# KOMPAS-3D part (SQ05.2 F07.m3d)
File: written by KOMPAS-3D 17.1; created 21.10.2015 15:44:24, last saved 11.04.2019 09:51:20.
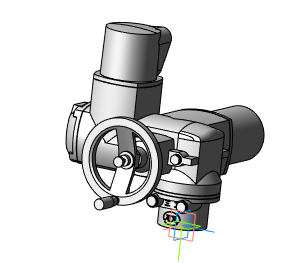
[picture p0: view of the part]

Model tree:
1. Операция без истории:4  (labels: Сталь 20  ГОСТ 1050-88)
